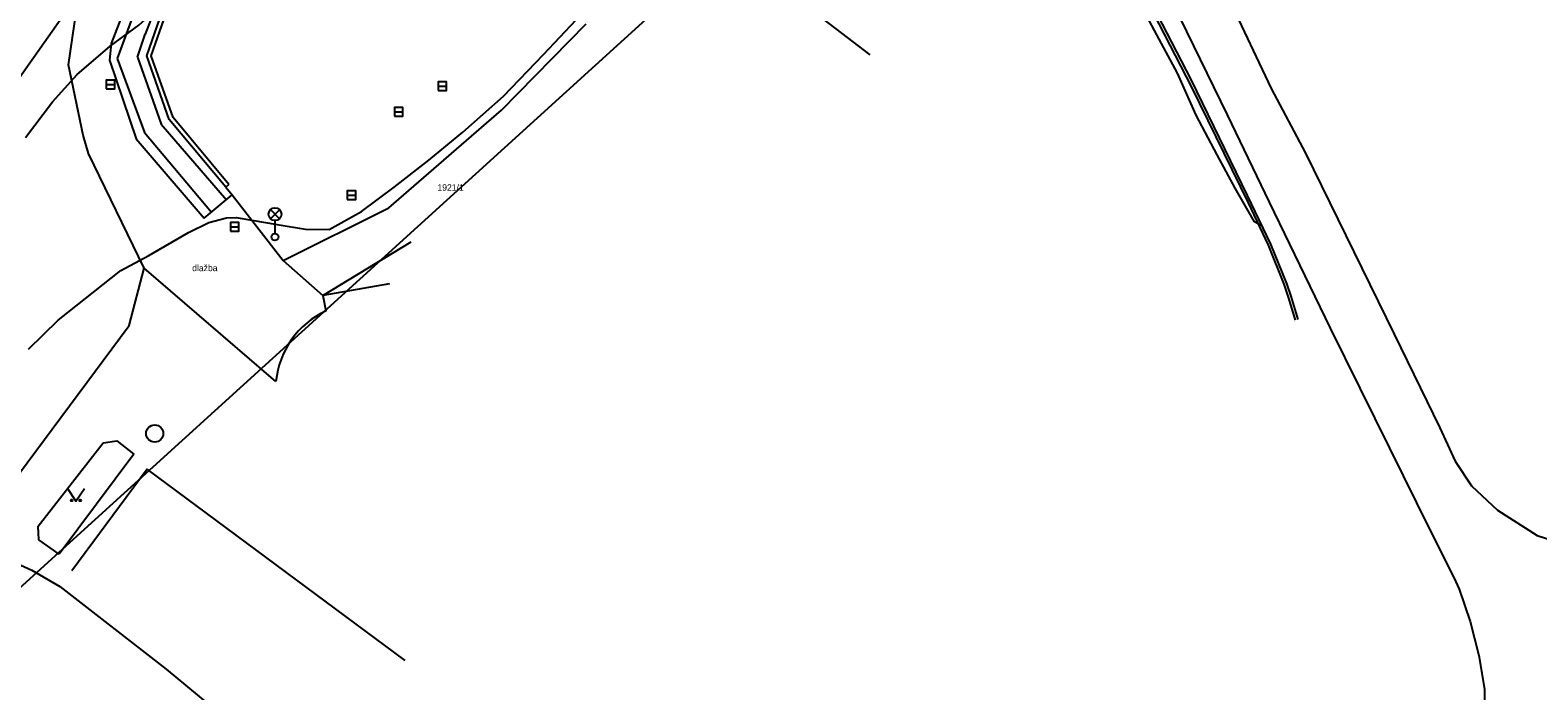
# Model space of a CAD drawing. Extents: x -756646 to -755837, y -1138704 to -1137865.
# Drawn here: x -756229.8 to -756053.9, y -1138577.6 to -1138500.6 of the extents above; entities that cross this region are included whole.
import ezdxf

# ---------------------------------------------------------------- set-up
doc = ezdxf.new("R2010")
doc.units = 0
for name, color, linetype in [('f001_n_feature_bunka', 7, 'Continuous'), ('f001_n_feature_linie', 7, 'Continuous'), ('f001_n_feature_text', 7, 'Continuous'), ('f002_n_feature_linie', 7, 'Continuous'), ('fsys_polygon_cinnost', 7, 'Continuous')]:
    doc.layers.add(name, color=color, linetype=linetype)

msp = doc.modelspace()

# ---------------------------------------------------------------- linework, layer by layer
at = {"layer": 'f001_n_feature_bunka'}
for p, q in [((-756220.89, -1138506.9), (-756219.89, -1138506.9)), ((-756182.17, -1138507.1), (-756181.17, -1138507.1)), ((-756187.26, -1138510.08), (-756186.26, -1138510.08)), ((-756192.75, -1138519.8), (-756191.75, -1138519.8)), ((-756201.72, -1138522.56), (-756200.66, -1138521.5)), ((-756200.65, -1138522.55), (-756201.7, -1138521.49)), ((-756206.39, -1138523.5), (-756205.39, -1138523.5)), ((-756201.19, -1138522.78), (-756201.19, -1138524.28))]:
    msp.add_line(p, q, dxfattribs=at)
for points in [[(-756220.89, -1138507.4), (-756219.89, -1138507.4), (-756219.89, -1138506.4), (-756220.89, -1138506.4)], [(-756182.17, -1138507.6), (-756181.17, -1138507.6), (-756181.17, -1138506.6), (-756182.17, -1138506.6)], [(-756187.26, -1138510.58), (-756186.26, -1138510.58), (-756186.26, -1138509.58), (-756187.26, -1138509.58)], [(-756192.75, -1138520.3), (-756191.75, -1138520.3), (-756191.75, -1138519.3), (-756192.75, -1138519.3)], [(-756206.39, -1138524), (-756205.39, -1138524), (-756205.39, -1138523), (-756206.39, -1138523)]]:
    msp.add_lwpolyline(points, close=True, dxfattribs=at)
msp.add_lwpolyline([(-756225.41, -1138554), (-756224.41, -1138555.5), (-756223.41, -1138554)], dxfattribs=at)
for centre, radius in [((-756201.19, -1138522.03), 0.75), ((-756201.19, -1138524.68), 0.4), ((-756215.22, -1138547.6), 1), ((-756224.91, -1138555.4), 0.1), ((-756223.91, -1138555.4), 0.1)]:
    msp.add_circle(centre, radius, dxfattribs=at)
at = {"layer": 'f001_n_feature_linie'}
for p, q in [((-756230.98, -1138506.1), (-756221.75, -1138492.95)), ((-756217.84, -1138495.72), (-756220.31, -1138502.14)), ((-756216.76, -1138496.15), (-756219.61, -1138503.89)), ((-756215.02, -1138497.6), (-756216.35, -1138501.02)), ((-756225.28, -1138504.62), (-756224.35, -1138498.25)), ((-756217.22, -1138503.7), (-756216.35, -1138501.02)), ((-756174.76, -1138509.9), (-756164.87, -1138499.84)), ((-756220.31, -1138502.14), (-756220.51, -1138504.08)), ((-756220.51, -1138504.08), (-756217.39, -1138513.24)), ((-756219.61, -1138503.89), (-756216.42, -1138512.51)), ((-756217.22, -1138503.7), (-756214.46, -1138511.52)), ((-756187.91, -1138521.28), (-756174.76, -1138509.9)), ((-756214.46, -1138511.52), (-756206.85, -1138520.35)), ((-756217.39, -1138513.24), (-756209.44, -1138522.49)), ((-756216.42, -1138512.51), (-756208.6, -1138521.78)), ((-756216.44, -1138528.33), (-756222.93, -1138514.97)), ((-756206.56, -1138518.55), (-756206.94, -1138518.87)), ((-756209.44, -1138522.49), (-756206.19, -1138519.78)), ((-756200.24, -1138527.41), (-756187.91, -1138521.28)), ((-756195.61, -1138531.51), (-756185.29, -1138525.24)), ((-756218.19, -1138535), (-756216.44, -1138528.33)), ((-756201.08, -1138541.55), (-756216.44, -1138528.33)), ((-756187.84, -1138530.14), (-756195.61, -1138531.51)), ((-756195.61, -1138531.51), (-756195.24, -1138533.3)), ((-756231.12, -1138552.39), (-756218.19, -1138535)), ((-756228.81, -1138558.42), (-756221.23, -1138548.68)), ((-756221.23, -1138548.68), (-756219.65, -1138548.46)), ((-756219.65, -1138548.46), (-756217.64, -1138550.01)), ((-756217.64, -1138550.01), (-756226.35, -1138561.66)), ((-756216.09, -1138551.76), (-756224.87, -1138563.6)), ((-756186.02, -1138574.05), (-756216.09, -1138551.76)), ((-756228.72, -1138560), (-756228.81, -1138558.42)), ((-756226.35, -1138561.66), (-756228.72, -1138560))]:
    msp.add_line(p, q, dxfattribs=at)
for points in [[(-756150.29, -1138442.85), (-756149.7, -1138443.67), (-756147.58, -1138442.47), (-756146.18, -1138441.95), (-756144.89, -1138441.84), (-756143.59, -1138442.01), (-756141.73, -1138442.66), (-756139.05, -1138444.54), (-756136.75, -1138446.78), (-756130.23, -1138453.68), (-756125.57, -1138458.77), (-756119.27, -1138466.14), (-756115.85, -1138470.25), (-756113.52, -1138473.62), (-756108.26, -1138481.09), (-756105.61, -1138485.47), (-756101.9, -1138492.39), (-756094.28, -1138507.21), (-756087.68, -1138520.72), (-756085.33, -1138525.64), (-756083.49, -1138530.2), (-756082.99, -1138531.69), (-756082.17, -1138534.4)], [(-756150.05, -1138442.67), (-756149.62, -1138443.27), (-756147.71, -1138442.19), (-756146.25, -1138441.65), (-756144.89, -1138441.54), (-756143.52, -1138441.71), (-756141.64, -1138442.39), (-756138.86, -1138444.31), (-756136.54, -1138446.57), (-756130, -1138453.48), (-756125.35, -1138458.57), (-756119.05, -1138465.94), (-756115.76, -1138469.81), (-756113.27, -1138473.45), (-756108.01, -1138480.92), (-756105.35, -1138485.32), (-756101.64, -1138492.25), (-756094.37, -1138506.32), (-756087.77, -1138519.83), (-756085.06, -1138525.52), (-756083.21, -1138530.09), (-756082.7, -1138531.6), (-756081.88, -1138534.31)], [(-756206.94, -1138518.87), (-756213.53, -1138510.99), (-756216.15, -1138503.58), (-756214.31, -1138498.31), (-756210.76, -1138494.63), (-756189.46, -1138477.18), (-756182.62, -1138471.1)], [(-756206.56, -1138518.55), (-756213.08, -1138510.74), (-756215.62, -1138503.58), (-756213.88, -1138498.58), (-756210.42, -1138494.99), (-756189.13, -1138477.56), (-756182.28, -1138471.48)], [(-756131.75, -1138503.45), (-756147.95, -1138491.04), (-756154.55, -1138491.93)], [(-756098.79, -1138492.63), (-756090.13, -1138510.45), (-756085.2, -1138520.61), (-756078.08, -1138535.33), (-756071.16, -1138549.31), (-756066.43, -1138558.92), (-756063.63, -1138564.48), (-756063.07, -1138565.76), (-756061.76, -1138569.51), (-756060.75, -1138573.49), (-756060.08, -1138577.42), (-756060.08, -1138581.43)], [(-756089.86, -1138497.1), (-756084.99, -1138507.37), (-756080.99, -1138514.93), (-756070.64, -1138536), (-756065.29, -1138546.92), (-756063.51, -1138550.81), (-756061.63, -1138553.69), (-756058.59, -1138556.52), (-756053.97, -1138559.49), (-756050.31, -1138560.64)], [(-756222.93, -1138514.97), (-756223.56, -1138512.8), (-756225.28, -1138504.62)], [(-756206.94, -1138518.87), (-756206.19, -1138519.78), (-756200.24, -1138527.41), (-756195.61, -1138531.51)]]:
    msp.add_lwpolyline(points, dxfattribs=at)
msp.add_arc((-756190.91, -1138542.55), 10.22, 115.0567, 174.3493, dxfattribs=at)
at = {"layer": 'f002_n_feature_linie'}
for points in [[(-756230.3, -1138513.08), (-756227.15, -1138508.93), (-756224.26, -1138505.73), (-756220.4, -1138502.44), (-756217.09, -1138499.98), (-756213.29, -1138496.57), (-756208.87, -1138492.67), (-756204.82, -1138489.23), (-756200.73, -1138485.69), (-756192.88, -1138478.85), (-756188.68, -1138475.64), (-756185.02, -1138472.75), (-756180.77, -1138469.24), (-756176.08, -1138465.1), (-756171.17, -1138460.99), (-756166.56, -1138457.38), (-756158.07, -1138450.09), (-756153.24, -1138446.1), (-756149.39, -1138442.64), (-756148.74, -1138442.43)], [(-756086.1, -1138523.39), (-756086.91, -1138522.9), (-756089.19, -1138519.01), (-756091.29, -1138515.12), (-756093.75, -1138510.5), (-756095.89, -1138505.57), (-756098.33, -1138501.13), (-756100.35, -1138497.34)], [(-756229.94, -1138537.76), (-756226.47, -1138534.38), (-756219.19, -1138528.58), (-756215.89, -1138526.86), (-756211.28, -1138524.17), (-756208.91, -1138522.99), (-756206.85, -1138522.45), (-756205.71, -1138522.4), (-756203.9, -1138522.71), (-756200.95, -1138523.23), (-756197.64, -1138523.78), (-756194.88, -1138523.82), (-756191.11, -1138521.71), (-756187.3, -1138518.88), (-756183.24, -1138515.73), (-756179.27, -1138512.45), (-756174.52, -1138508.28), (-756169.85, -1138503.39), (-756166.05, -1138499.36)], [(-756232.53, -1138562.16), (-756229.54, -1138563.55), (-756226.27, -1138565.44), (-756213.88, -1138575.09), (-756208.91, -1138579.18)]]:
    msp.add_lwpolyline(points, dxfattribs=at)
at = {"layer": 'fsys_polygon_cinnost'}
msp.add_lwpolyline([(-756221, -1138292), (-756383, -1138432), (-756376, -1138555), (-756270, -1138601), (-756075, -1138424), (-756086, -1138402)], close=True, dxfattribs=at)

# ---------------------------------------------------------------- texts
at = {"layer": 'f001_n_feature_text'}
for s, p in [('1921/1', (-756182.24, -1138519.29)), ('dlažba', (-756210.85, -1138528.67))]:
    msp.add_text(s, height=0.75, dxfattribs=at).set_placement(p)

doc.saveas('drawing.dxf')
